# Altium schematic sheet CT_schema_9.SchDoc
size 252 x 159 mm
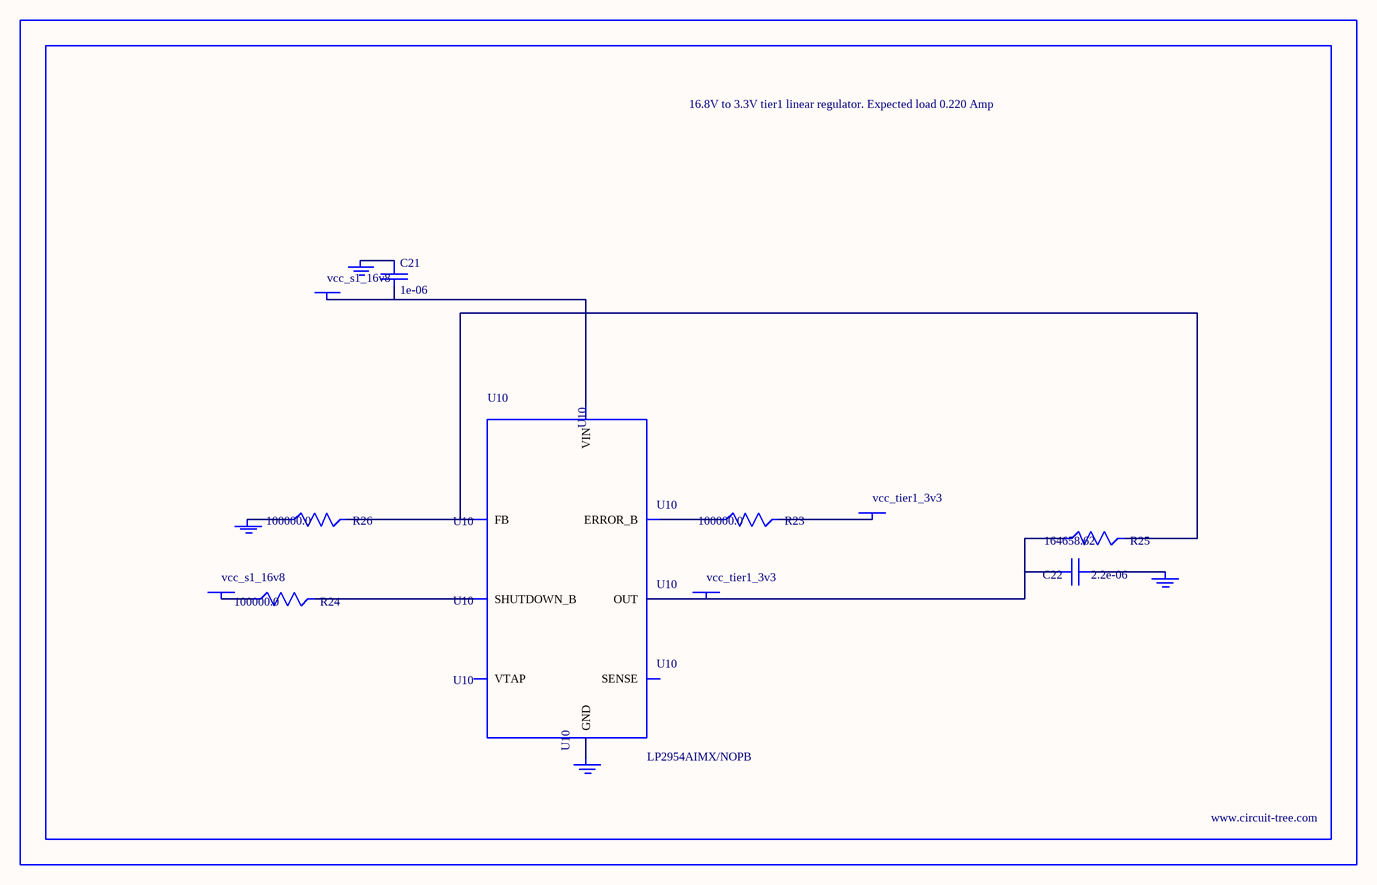
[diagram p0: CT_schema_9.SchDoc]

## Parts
BORDER8  (no value)
C21  1e-06  [EXV-9B]
C22  2.2e-06  [EXV-9B]
GND_INSTANCE_8_0  (no value)
GND_INSTANCE_8_1  (no value)
GND_INSTANCE_8_2  (no value)
GND_INSTANCE_8_3  (no value)
POWER_INSTANCE_8_0  vcc_s1_16v8
POWER_INSTANCE_8_1  vcc_tier1_3v3
POWER_INSTANCE_8_2  vcc_s1_16v8
POWER_INSTANCE_8_3  vcc_tier1_3v3
R23  100000.0  [R0603]
R24  100000.0  [R0603]
R25  164658.62  [R0603]
R26  100000.0  [R0603]
U10  LP2954AIMX/NOPB  [LP2954]

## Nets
NetC21_1: C21.1 GND_INSTANCE_8_2.0(GND)
NetC21_2: C21.2 POWER_INSTANCE_8_2.0(PWR) U10.8(VIN)
NetC22_1: C22.1 GND_INSTANCE_8_0.0(GND)
NetC22_2: C22.2 POWER_INSTANCE_8_3.0(PWR) R25.1 U10.1(OUT)
NetGND_INSTANCE_8_1_0: GND_INSTANCE_8_1.0(GND) R26.1
NetGND_INSTANCE_8_3_0: GND_INSTANCE_8_3.0(GND) U10.4(GND)
NetPOWER_INSTANCE_8_0_0: POWER_INSTANCE_8_0.0(PWR) R24.1
NetPOWER_INSTANCE_8_1_0: POWER_INSTANCE_8_1.0(PWR) R23.2
NetR23_1: R23.1 U10.5(ERROR_B)
NetR24_2: R24.2 U10.3(SHUTDOWN_B)
NetR25_2: R25.2 R26.2 U10.7(FB)

Not connected (* = marked no-connect by the designer): U10 2(SENSE) 6(VTAP)

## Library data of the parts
BORDER8 = BORDER_PAGE8
C21 = EDK105M050A9BAA
C22 = EDK225M050A9BAA
GND_INSTANCE_8_0-GND_INSTANCE_8_3 = GND
POWER_INSTANCE_8_0-POWER_INSTANCE_8_3 = PWR
R23 R24 R26 = RC0603JR-07100KL
R25 = R25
